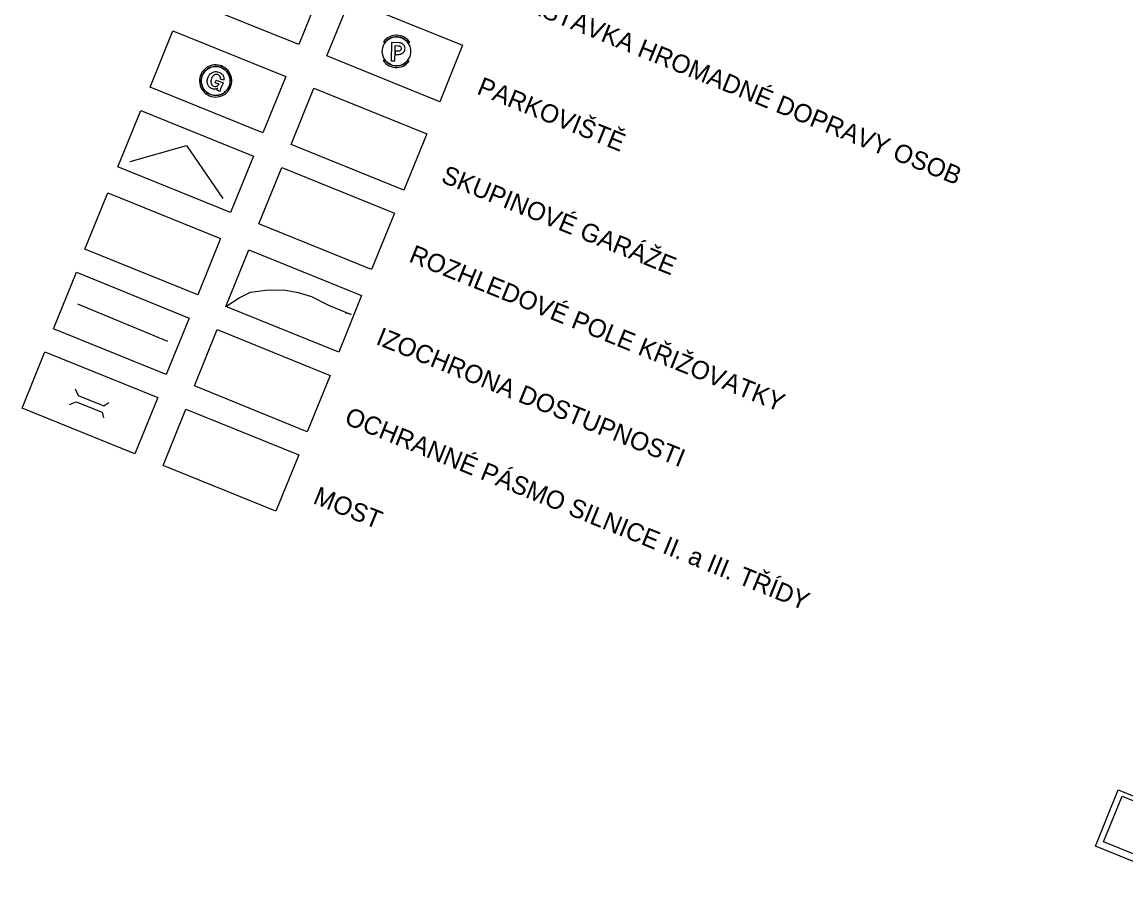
# Model space of a CAD drawing. Extents: x -522797 to -519326, y -1191143 to -1184078.
# Drawn here: x -522797 to -521890, y -1190366 to -1189651 of the extents above; entities that cross this region are included whole.
import ezdxf

# ---------------------------------------------------------------- set-up
doc = ezdxf.new("R2010")
doc.units = 0
for name, color, linetype in [('Implicitní', 7, 'Continuous'), ('ložisk_nerost', 7, 'Continuous'), ('most_s', 7, 'Continuous'), ('odvodneni_s', 7, 'Continuous'), ('OP_sil_IIaIII_s', 7, 'Continuous'), ('rozhled_pole_s', 7, 'Continuous')]:
    doc.layers.add(name, color=color, linetype=linetype)

msp = doc.modelspace()

# ---------------------------------------------------------------- linework, layer by layer
at = {"layer": 'Implicitní'}
for points in [[(-522643.3, -1189585.46), (-522550.63, -1189623.02), (-522569.41, -1189669.36), (-522662.08, -1189631.8)], [(-522527.46, -1189632.41), (-522434.78, -1189669.97), (-522453.56, -1189716.31), (-522546.24, -1189678.75)], [(-522672.75, -1189658.12), (-522580.07, -1189695.68), (-522598.86, -1189742.02), (-522691.53, -1189704.46)], [(-522556.91, -1189705.07), (-522464.23, -1189742.63), (-522483.01, -1189788.97), (-522575.69, -1189751.41)], [(-522699.21, -1189723.41), (-522606.54, -1189760.97), (-522625.32, -1189807.31), (-522717.99, -1189769.75)], [(-522583.37, -1189770.36), (-522490.69, -1189807.92), (-522509.47, -1189854.26), (-522602.15, -1189816.7)], [(-522726.33, -1189791.2), (-522633.64, -1189828.75), (-522652.41, -1189875.09), (-522745.1, -1189837.54)], [(-522610.47, -1189838.13), (-522517.79, -1189875.67), (-522536.56, -1189922.02), (-522629.24, -1189884.47)], [(-522752.1, -1189856.5), (-522659.45, -1189894.13), (-522678.26, -1189940.45), (-522770.91, -1189902.83)], [(-522636.29, -1189903.53), (-522543.63, -1189941.15), (-522562.44, -1189987.48), (-522655.1, -1189949.86)], [(-522777.88, -1189921.81), (-522685.22, -1189959.43), (-522704.03, -1190005.75), (-522796.69, -1189968.13)], [(-522662.06, -1189968.83), (-522569.41, -1190006.45), (-522588.22, -1190052.78), (-522680.87, -1190015.16)], [(-521896.02, -1190281.7), (-521803.34, -1190319.26), (-521822.13, -1190365.6), (-521914.8, -1190328.04)]]:
    msp.add_lwpolyline(points, close=True, dxfattribs=at)
msp.add_lwpolyline([(-522707.91, -1189765.56), (-522661.56, -1189752.18), (-522631.69, -1189795.72)], dxfattribs=at)
at = {"layer": 'ložisk_nerost'}
for points in [[(-522477.2, -1189675.19), (-522477.26, -1189673.69), (-522477.51, -1189672.21), (-522477.95, -1189670.77), (-522478.57, -1189669.4), (-522479.35, -1189668.12), (-522480.29, -1189666.94), (-522481.37, -1189665.9), (-522482.57, -1189664.99), (-522483.87, -1189664.25), (-522485.26, -1189663.68), (-522486.72, -1189663.29), (-522488.2, -1189663.08), (-522489.71, -1189663.06), (-522491.2, -1189663.24), (-522492.66, -1189663.6), (-522494.06, -1189664.14), (-522495.38, -1189664.85), (-522496.61, -1189665.73), (-522497.71, -1189666.75), (-522498.67, -1189667.9), (-522499.48, -1189669.17), (-522500.13, -1189670.53), (-522500.6, -1189671.95), (-522500.88, -1189673.43), (-522500.98, -1189674.93), (-522500.88, -1189676.43), (-522500.6, -1189677.91), (-522500.13, -1189679.33), (-522499.49, -1189680.69), (-522498.68, -1189681.96), (-522497.71, -1189683.11), (-522496.61, -1189684.14), (-522495.39, -1189685.01), (-522494.07, -1189685.73), (-522492.67, -1189686.27), (-522491.21, -1189686.63), (-522489.72, -1189686.81), (-522488.21, -1189686.79), (-522486.73, -1189686.59), (-522485.27, -1189686.2), (-522483.88, -1189685.62), (-522482.58, -1189684.88), (-522481.37, -1189683.98), (-522480.29, -1189682.94), (-522479.35, -1189681.76), (-522478.57, -1189680.48), (-522477.95, -1189679.11), (-522477.52, -1189677.67), (-522477.26, -1189676.19), (-522477.2, -1189675.19)], [(-522488.82, -1189661.73), (-522489.64, -1189661.74), (-522491.3, -1189661.91), (-522492.93, -1189662.29), (-522494.49, -1189662.88), (-522495.97, -1189663.65), (-522497.34, -1189664.61), (-522498.58, -1189665.74), (-522499.66, -1189667)], [(-522497.99, -1189667.04), (-522497.1, -1189666.14), (-522495.92, -1189665.2), (-522494.64, -1189664.42), (-522493.27, -1189663.8), (-522491.83, -1189663.37), (-522490.35, -1189663.11), (-522488.85, -1189663.05)], [(-522488.83, -1189663.05), (-522487.57, -1189663.14), (-522486.09, -1189663.43), (-522484.67, -1189663.9), (-522483.31, -1189664.55), (-522482.05, -1189665.36), (-522480.89, -1189666.33), (-522479.87, -1189667.43)], [(-522478.2, -1189667.47), (-522478.69, -1189666.8), (-522479.8, -1189665.56), (-522481.06, -1189664.46), (-522482.44, -1189663.53), (-522483.93, -1189662.78), (-522485.51, -1189662.22), (-522487.14, -1189661.87), (-522488.81, -1189661.73)], [(-522499.66, -1189667), (-522497.99, -1189667.04)], [(-522486.76, -1189667.86), (-522493.21, -1189667.72), (-522493.53, -1189682.6), (-522490.37, -1189682.67), (-522490.2, -1189674.82)], [(-522490.2, -1189674.82), (-522490.1, -1189670.25)], [(-522490.15, -1189674.82), (-522490.2, -1189677.4)], [(-522487.62, -1189674.87), (-522490.15, -1189674.82)], [(-522490.1, -1189670.25), (-522487.52, -1189670.3)], [(-522487.52, -1189670.3), (-522487.4, -1189670.31), (-522487.29, -1189670.31), (-522486.7, -1189670.44), (-522486.47, -1189670.56), (-522486.24, -1189670.68), (-522486.01, -1189670.81), (-522485.78, -1189671.05), (-522485.55, -1189671.29), (-522485.32, -1189671.64), (-522485.21, -1189672), (-522485.11, -1189672.58), (-522485.11, -1189672.82), (-522485.24, -1189673.29), (-522485.36, -1189673.64), (-522485.61, -1189673.98), (-522485.73, -1189674.1), (-522485.97, -1189674.33), (-522486.32, -1189674.55), (-522486.56, -1189674.66), (-522486.91, -1189674.77), (-522487.38, -1189674.88), (-522487.62, -1189674.87)], [(-522486.97, -1189677.47), (-522486.27, -1189677.37), (-522485.79, -1189677.26), (-522485.44, -1189677.15), (-522485.09, -1189677.04), (-522484.85, -1189676.93), (-522484.61, -1189676.82), (-522484.26, -1189676.59), (-522483.9, -1189676.36), (-522483.66, -1189676.13), (-522483.42, -1189675.9), (-522483.18, -1189675.68), (-522482.94, -1189675.33), (-522482.7, -1189674.98), (-522482.57, -1189674.75), (-522482.45, -1189674.52), (-522482.33, -1189674.17), (-522482.2, -1189673.82), (-522482.07, -1189673.24), (-522482.07, -1189672.88), (-522482.06, -1189672.42), (-522482.16, -1189671.83), (-522482.16, -1189671.71), (-522482.27, -1189671.36), (-522482.38, -1189671), (-522482.6, -1189670.53), (-522482.83, -1189670.17), (-522483.05, -1189669.81), (-522483.28, -1189669.57), (-522483.51, -1189669.34), (-522483.74, -1189669.1), (-522484.09, -1189668.85), (-522484.43, -1189668.61), (-522484.67, -1189668.49), (-522484.9, -1189668.37), (-522485.25, -1189668.24), (-522485.48, -1189668.12), (-522486.06, -1189667.99), (-522486.76, -1189667.86)], [(-522479.87, -1189667.43), (-522478.2, -1189667.47)], [(-522499.99, -1189682.4), (-522498.97, -1189683.71), (-522497.79, -1189684.88), (-522496.46, -1189685.9), (-522495.02, -1189686.74), (-522493.48, -1189687.4), (-522491.88, -1189687.85), (-522490.22, -1189688.1), (-522488.55, -1189688.13), (-522486.89, -1189687.96), (-522485.27, -1189687.58), (-522483.7, -1189686.99), (-522482.22, -1189686.22), (-522480.86, -1189685.26), (-522479.62, -1189684.14), (-522478.54, -1189682.87)], [(-522498.32, -1189682.44), (-522499.99, -1189682.4)], [(-522480.21, -1189682.83), (-522480.94, -1189683.58), (-522482.09, -1189684.54), (-522483.36, -1189685.35), (-522484.72, -1189685.99), (-522486.15, -1189686.45), (-522487.62, -1189686.73), (-522489.13, -1189686.82), (-522490.63, -1189686.73), (-522492.1, -1189686.44), (-522493.53, -1189685.97), (-522494.88, -1189685.32), (-522496.15, -1189684.51), (-522497.3, -1189683.54), (-522498.32, -1189682.44)], [(-522490.2, -1189677.4), (-522486.97, -1189677.47)], [(-522478.54, -1189682.87), (-522480.21, -1189682.83)], [(-522629.24, -1189884.47), (-522618.2, -1189877.43), (-522609.09, -1189872.86), (-522596.67, -1189871.12), (-522581.49, -1189870.88), (-522569.77, -1189873), (-522559.02, -1189876.36), (-522544.79, -1189883.43), (-522526.21, -1189891.23), (-522530.91, -1189889.9)]]:
    msp.add_lwpolyline(points, dxfattribs=at)
at = {"layer": 'most_s'}
for points in [[(-522752.99, -1189952.23), (-522750.73, -1189957.6), (-522729.48, -1189966.18), (-522725.33, -1189963.57)], [(-522757.61, -1189965.24), (-522752.27, -1189962.93), (-522730.98, -1189971.43), (-522729.79, -1189976.18)]]:
    msp.add_lwpolyline(points, dxfattribs=at)
at = {"layer": 'odvodneni_s'}
msp.add_lwpolyline([(-521892.81, -1190286.84), (-521808.94, -1190320.84), (-521824.15, -1190358.37), (-521908.02, -1190324.38)], close=True, dxfattribs=at)
at = {"layer": 'OP_sil_IIaIII_s'}
msp.add_line((-522751.19, -1189882.51), (-522677.23, -1189912.98), dxfattribs=at)
at = {"layer": 'rozhled_pole_s'}
for points in [[(-522632.86, -1189686.92), (-522633.9, -1189686.57), (-522635.53, -1189686.2), (-522637.19, -1189686.04), (-522638.86, -1189686.09), (-522640.51, -1189686.35), (-522642.11, -1189686.82), (-522643.64, -1189687.49), (-522645.08, -1189688.34), (-522646.39, -1189689.37), (-522647.57, -1189690.55), (-522648.59, -1189691.88), (-522649.43, -1189693.32), (-522650.08, -1189694.86), (-522650.54, -1189696.47), (-522650.78, -1189698.12), (-522650.82, -1189699.79), (-522650.65, -1189701.45), (-522650.26, -1189703.07), (-522649.68, -1189704.64), (-522648.9, -1189706.12), (-522647.95, -1189707.48), (-522646.82, -1189708.72), (-522645.55, -1189709.81), (-522644.16, -1189710.72), (-522642.66, -1189711.45), (-522641.08, -1189711.99), (-522639.44, -1189712.33), (-522637.77, -1189712.45), (-522636.11, -1189712.36), (-522634.46, -1189712.07), (-522632.87, -1189711.57), (-522631.35, -1189710.87), (-522629.94, -1189709.99), (-522628.64, -1189708.93), (-522627.49, -1189707.72), (-522626.5, -1189706.37), (-522625.69, -1189704.91), (-522625.07, -1189703.36), (-522624.65, -1189701.75), (-522624.44, -1189700.09), (-522624.44, -1189698.42), (-522624.65, -1189696.76), (-522625.06, -1189695.15), (-522625.68, -1189693.6), (-522626.49, -1189692.13), (-522627.48, -1189690.79), (-522628.63, -1189689.57), (-522629.92, -1189688.52), (-522631.33, -1189687.63), (-522632.85, -1189686.93)], [(-522626.54, -1189703.54), (-522626.08, -1189702.1), (-522625.81, -1189700.62), (-522625.73, -1189699.12), (-522625.84, -1189697.62), (-522626.14, -1189696.15), (-522626.62, -1189694.73), (-522627.28, -1189693.38), (-522628.11, -1189692.12), (-522629.08, -1189690.97), (-522630.19, -1189689.96), (-522631.42, -1189689.1), (-522632.75, -1189688.4), (-522634.16, -1189687.87), (-522635.62, -1189687.52), (-522637.12, -1189687.37), (-522638.62, -1189687.4), (-522640.11, -1189687.62), (-522641.55, -1189688.02), (-522642.94, -1189688.61), (-522644.24, -1189689.37), (-522645.43, -1189690.28), (-522646.5, -1189691.34), (-522647.43, -1189692.52), (-522648.2, -1189693.81), (-522648.8, -1189695.19), (-522649.22, -1189696.63), (-522649.46, -1189698.11), (-522649.51, -1189699.62), (-522649.36, -1189701.11), (-522649.03, -1189702.58), (-522648.52, -1189703.99), (-522647.84, -1189705.33), (-522646.99, -1189706.57), (-522645.99, -1189707.69), (-522644.85, -1189708.68), (-522643.61, -1189709.52), (-522642.26, -1189710.19), (-522640.84, -1189710.69), (-522639.37, -1189711), (-522637.88, -1189711.13), (-522636.37, -1189711.07), (-522634.89, -1189710.81), (-522633.45, -1189710.38), (-522632.08, -1189709.76), (-522630.8, -1189708.98), (-522629.63, -1189708.04), (-522628.58, -1189706.96), (-522627.68, -1189705.76), (-522626.94, -1189704.45), (-522626.54, -1189703.54)], [(-522633.32, -1189688.16), (-522632.42, -1189688.55), (-522631.11, -1189689.3), (-522629.91, -1189690.2), (-522628.83, -1189691.24), (-522627.89, -1189692.42), (-522627.11, -1189693.7), (-522626.49, -1189695.07), (-522626.05, -1189696.51), (-522625.8, -1189697.99), (-522625.74, -1189699.49), (-522625.86, -1189700.99), (-522626.18, -1189702.46), (-522626.67, -1189703.88), (-522627.35, -1189705.22), (-522628.18, -1189706.47), (-522629.17, -1189707.6), (-522630.29, -1189708.6), (-522631.53, -1189709.45), (-522632.87, -1189710.14), (-522634.28, -1189710.65), (-522635.75, -1189710.98), (-522637.24, -1189711.13), (-522638.75, -1189711.08), (-522640.23, -1189710.84), (-522641.67, -1189710.42), (-522643.05, -1189709.82), (-522644.34, -1189709.05), (-522645.53, -1189708.12), (-522646.58, -1189707.06), (-522647.5, -1189705.86), (-522648.25, -1189704.56), (-522648.84, -1189703.18), (-522649.25, -1189701.73), (-522649.47, -1189700.25), (-522649.5, -1189698.74), (-522649.34, -1189697.25), (-522649, -1189695.79), (-522648.47, -1189694.38), (-522647.77, -1189693.05), (-522646.91, -1189691.82), (-522645.9, -1189690.71), (-522644.75, -1189689.73), (-522643.49, -1189688.91), (-522642.14, -1189688.25), (-522640.72, -1189687.77), (-522639.25, -1189687.47), (-522637.75, -1189687.36), (-522636.25, -1189687.44), (-522634.77, -1189687.7), (-522633.33, -1189688.15)], [(-522642.87, -1189694.49), (-522642.46, -1189694.05)], [(-522642.46, -1189694.05), (-522642.02, -1189693.51)], [(-522642.02, -1189693.51), (-522641.5, -1189693.11)], [(-522641.5, -1189693.11), (-522641.14, -1189692.78)], [(-522641.14, -1189692.78), (-522640.81, -1189692.55)], [(-522640.81, -1189692.55), (-522639.23, -1189691.85)], [(-522639.23, -1189691.85), (-522638.06, -1189691.59)], [(-522637.93, -1189694.02), (-522638.64, -1189694.34)], [(-522638.06, -1189691.59), (-522637.81, -1189691.57)], [(-522637.68, -1189694), (-522637.93, -1189694.02)], [(-522637.81, -1189691.57), (-522637.21, -1189691.56)], [(-522637.29, -1189693.91), (-522637.68, -1189694)], [(-522636.69, -1189693.91), (-522637.29, -1189693.91)], [(-522637.21, -1189691.56), (-522636.3, -1189691.67)], [(-522636.23, -1189693.96), (-522636.69, -1189693.91)], [(-522636.3, -1189691.67), (-522635.22, -1189691.97)], [(-522635.41, -1189694.28), (-522636.23, -1189693.96)], [(-522635.22, -1189691.97), (-522634.39, -1189692.29)], [(-522634.39, -1189692.29), (-522633.61, -1189692.72)], [(-522633.61, -1189692.72), (-522633.13, -1189693.02)], [(-522633.33, -1189688.15), (-522632.86, -1189686.92)], [(-522632.85, -1189686.93), (-522633.32, -1189688.16)], [(-522633.13, -1189693.02), (-522632.86, -1189693.24)], [(-522632.86, -1189693.24), (-522632.59, -1189693.47)], [(-522632.59, -1189693.47), (-522632.26, -1189693.84)], [(-522632.26, -1189693.84), (-522631.86, -1189694.35)], [(-522644.54, -1189700.04), (-522644.49, -1189698.98)], [(-522644.52, -1189700.28), (-522644.54, -1189700.04)], [(-522644.5, -1189700.53), (-522644.52, -1189700.28)], [(-522644.41, -1189700.92), (-522644.5, -1189700.53)], [(-522644.49, -1189698.98), (-522644.38, -1189698.07)], [(-522644.3, -1189701.56), (-522644.41, -1189700.92)], [(-522644.38, -1189698.07), (-522644.28, -1189697.52)], [(-522643.54, -1189703.28), (-522644.3, -1189701.56)], [(-522644.28, -1189697.52), (-522644.14, -1189696.86)], [(-522644.14, -1189696.86), (-522643.9, -1189696.23)], [(-522643.9, -1189696.23), (-522642.87, -1189694.49)], [(-522641.53, -1189699.65), (-522641.59, -1189700.11)], [(-522641.59, -1189700.11), (-522641.37, -1189701.38)], [(-522641.52, -1189699.3), (-522641.53, -1189699.65)], [(-522641.4, -1189698.39), (-522641.52, -1189699.3)], [(-522641.16, -1189697.77), (-522641.4, -1189698.39)], [(-522641.37, -1189701.38), (-522641.31, -1189701.53)], [(-522641.31, -1189701.53), (-522641.18, -1189701.82)], [(-522641.18, -1189701.82), (-522641.05, -1189702.1)], [(-522640.68, -1189696.53), (-522641.16, -1189697.77)], [(-522641.05, -1189702.1), (-522640.89, -1189702.29)], [(-522640.89, -1189702.29), (-522640.66, -1189702.61)], [(-522640.42, -1189696.15), (-522640.68, -1189696.53)], [(-522640.66, -1189702.61), (-522640.22, -1189703.02)], [(-522640.16, -1189695.78), (-522640.42, -1189696.15)], [(-522640.22, -1189703.02), (-522639.84, -1189703.29)], [(-522639.93, -1189695.51), (-522640.16, -1189695.78)], [(-522639.67, -1189695.13), (-522639.93, -1189695.51)], [(-522639.15, -1189694.74), (-522639.67, -1189695.13)], [(-522638.64, -1189694.34), (-522639.15, -1189694.74)], [(-522638, -1189700.67), (-522637.19, -1189698.59)], [(-522634.78, -1189701.91), (-522638, -1189700.67)], [(-522637.19, -1189698.59), (-522634.19, -1189699.76)], [(-522636.15, -1189703.29), (-522635.83, -1189703.05)], [(-522635.83, -1189703.05), (-522635.27, -1189702.55)], [(-522634.93, -1189694.59), (-522635.41, -1189694.28)], [(-522635.27, -1189702.55), (-522635.05, -1189702.28)], [(-522635.05, -1189702.28), (-522634.78, -1189701.91)], [(-522634.66, -1189694.81), (-522634.93, -1189694.59)], [(-522634.39, -1189695.03), (-522634.66, -1189694.81)], [(-522633.99, -1189695.55), (-522634.39, -1189695.03)], [(-522634.19, -1189699.76), (-522631.6, -1189700.76)], [(-522633.8, -1189695.98), (-522633.99, -1189695.55)], [(-522633.73, -1189696.12), (-522633.8, -1189695.98)], [(-522633.59, -1189696.66), (-522633.73, -1189696.12)], [(-522633.54, -1189697.15), (-522633.59, -1189696.66)], [(-522633.57, -1189697.85), (-522633.54, -1189697.15)], [(-522630.94, -1189698.75), (-522633.57, -1189697.85)], [(-522632.12, -1189702.1), (-522632.8, -1189703.87)], [(-522631.6, -1189700.76), (-522632.12, -1189702.1)], [(-522631.86, -1189694.35), (-522631.56, -1189694.82)], [(-522631.56, -1189694.82), (-522631.44, -1189695.11)], [(-522631.44, -1189695.11), (-522631.18, -1189695.68)], [(-522631.18, -1189695.68), (-522631.03, -1189696.22)], [(-522631.03, -1189696.22), (-522630.95, -1189696.61)], [(-522630.95, -1189696.61), (-522630.81, -1189697.49)], [(-522630.85, -1189698.19), (-522630.94, -1189698.75)], [(-522630.83, -1189697.84), (-522630.85, -1189698.19)], [(-522630.81, -1189697.49), (-522630.83, -1189697.84)], [(-522643.14, -1189703.8), (-522643.54, -1189703.28)], [(-522642.91, -1189704.12), (-522643.14, -1189703.8)], [(-522642.74, -1189704.31), (-522642.91, -1189704.12)], [(-522642.47, -1189704.53), (-522642.74, -1189704.31)], [(-522642.3, -1189704.72), (-522642.47, -1189704.53)], [(-522641.93, -1189704.98), (-522642.3, -1189704.72)], [(-522641.66, -1189705.2), (-522641.93, -1189704.98)], [(-522640.97, -1189705.59), (-522641.66, -1189705.2)], [(-522640.25, -1189705.87), (-522640.97, -1189705.59)], [(-522639.59, -1189706), (-522640.25, -1189705.87)], [(-522639.84, -1189703.29), (-522639.12, -1189703.57)], [(-522638.68, -1189706.12), (-522639.59, -1189706)], [(-522639.12, -1189703.57), (-522638.46, -1189703.7)], [(-522637.94, -1189706.05), (-522638.68, -1189706.12)], [(-522638.46, -1189703.7), (-522638, -1189703.76)], [(-522638, -1189703.76), (-522637.51, -1189703.71)], [(-522637.54, -1189705.96), (-522637.94, -1189706.05)], [(-522637.01, -1189705.81), (-522637.54, -1189705.96)], [(-522637.51, -1189703.71), (-522636.87, -1189703.6)], [(-522636.58, -1189705.62), (-522637.01, -1189705.81)], [(-522636.87, -1189703.6), (-522636.73, -1189703.54)], [(-522636.73, -1189703.54), (-522636.15, -1189703.29)], [(-522635.97, -1189705.26), (-522636.58, -1189705.62)], [(-522636.5, -1189706.96), (-522635.97, -1189705.26)], [(-522634.33, -1189707.8), (-522636.5, -1189706.96)], [(-522633.53, -1189705.73), (-522634.33, -1189707.8)], [(-522632.8, -1189703.87), (-522633.53, -1189705.73)]]:
    msp.add_lwpolyline(points, dxfattribs=at)

# ---------------------------------------------------------------- texts
at = {"layer": 'Implicitní'}
for s, rotation, p in [('ZASTÁVKA HROMADNÉ DOPRAVY OSOB', 337.93793, (-522394.37, -1189636.82)), ('PARKOVIŠTĚ', 337.93793, (-522423.82, -1189709.48)), ('SKUPINOVÉ GARÁŽE', 337.93793, (-522453.27, -1189782.14)), ('ROZHLEDOVÉ POLE KŘIŽOVATKY', 337.93793, (-522479.73, -1189847.43)), ('IZOCHRONA DOSTUPNOSTI', 337.94866, (-522506.82, -1189915.18)), ('OCHRANNÉ PÁSMO SILNICE II. a III. TŘÍDY', 337.90048, (-522532.7, -1189980.67)), ('MOST', 337.90048, (-522558.47, -1190045.97))]:
    msp.add_text(s, height=15, rotation=rotation, dxfattribs=at).set_placement(p)

doc.saveas('drawing.dxf')
